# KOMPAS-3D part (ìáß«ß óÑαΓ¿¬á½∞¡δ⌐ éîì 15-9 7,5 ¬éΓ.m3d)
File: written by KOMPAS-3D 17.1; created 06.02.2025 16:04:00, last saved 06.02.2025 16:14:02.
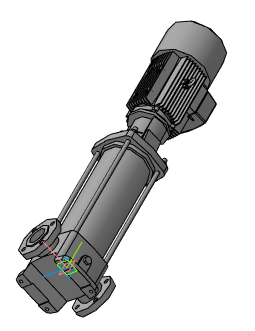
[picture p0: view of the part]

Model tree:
1. Операция без истории:1  (labels: Насос вертикальный ВМН 15-9 7,5 кВт)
